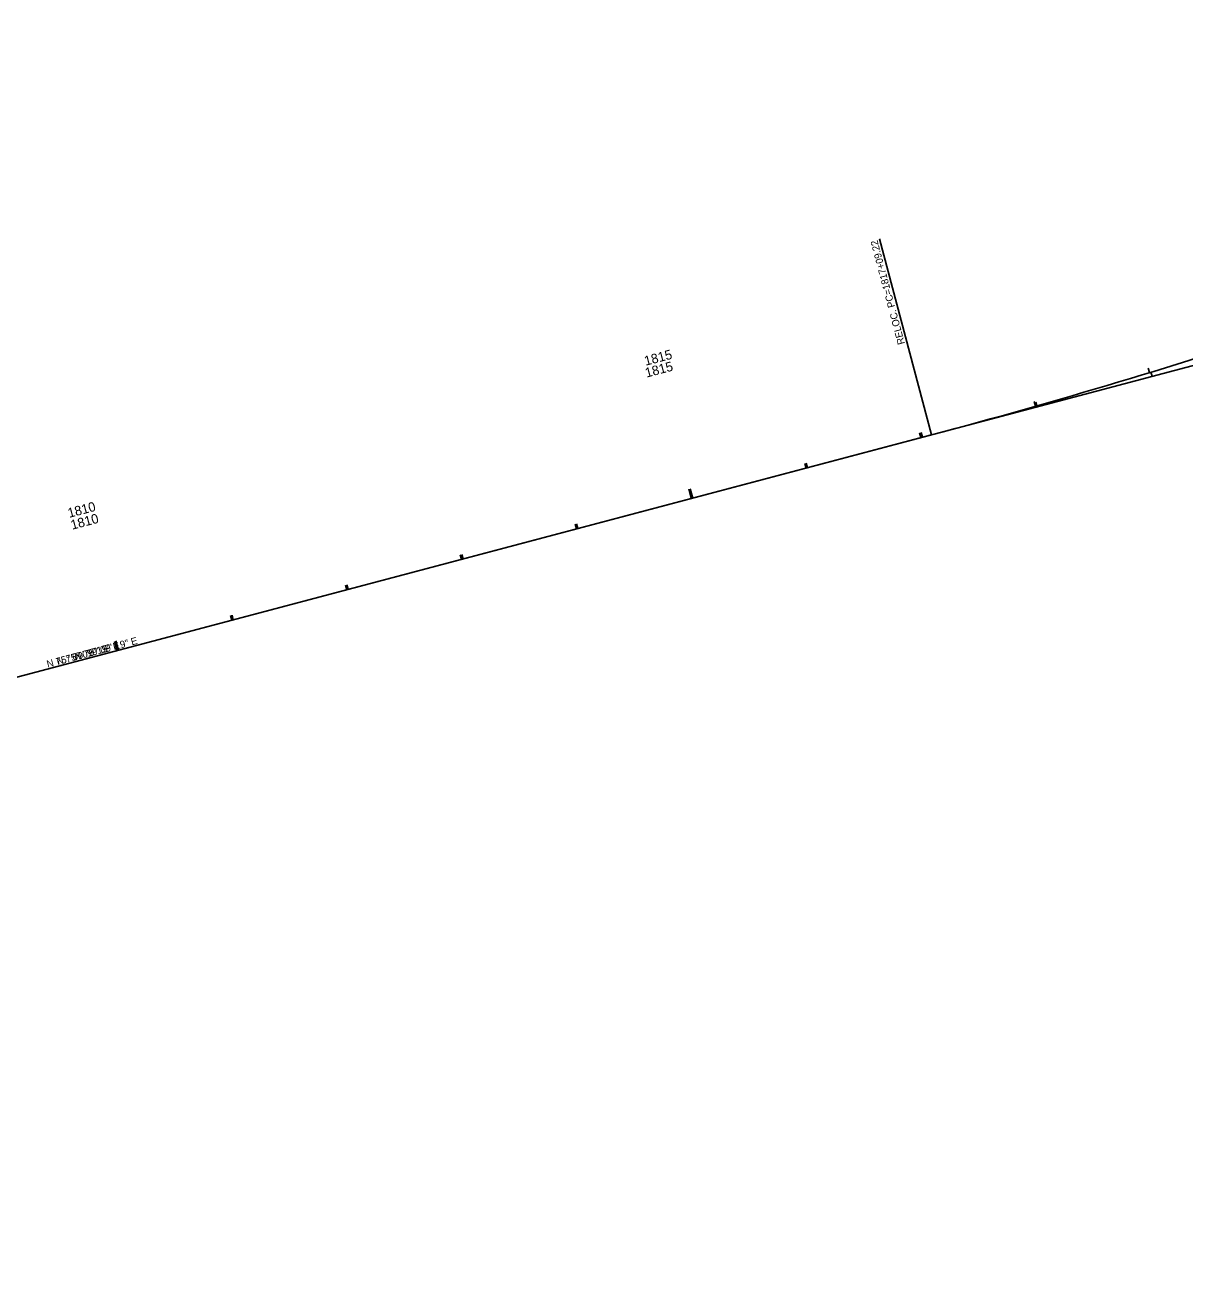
# Model space of a CAD drawing. Extents: x 2106154 to 2121963, y 864504 to 868517.
# Drawn here: x 2112014 to 2112990, y 867153 to 868210 of the extents above; entities that cross this region are included whole.
import ezdxf

# ---------------------------------------------------------------- set-up
doc = ezdxf.new("R2010")
doc.units = 0
for name, color, linetype in [('RD_HC_Cl', 7, 'Continuous'), ('RD_HC_CL_Rel', 7, 'Continuous'), ('RD_HC_Data', 7, 'Continuous'), ('RD_HC_Data_Rel', 7, 'Continuous'), ('RD_HC_Data_Tic', 7, 'Continuous'), ('RD_HC_Data_Tic_Rel', 7, 'Continuous'), ('RD_HC_TX_Rel_Sta50', 7, 'Continuous'), ('RD_HC_TX_Sta50', 7, 'Continuous')]:
    doc.layers.add(name, color=color, linetype=linetype)

msp = doc.modelspace()

# ---------------------------------------------------------------- linework, layer by layer
at = {"layer": 'RD_HC_Cl'}
msp.add_line((2110088.7, 867152.7), (2114077.7, 868210), dxfattribs=at)
at = {"layer": 'RD_HC_CL_Rel'}
msp.add_line((2111359.8, 867489.6), (2112776.4, 867865.1), dxfattribs=at)
msp.add_arc((2111482.6, 872746.5), 5050, 284.8448, 288.5627, dxfattribs=at)
at = {"layer": 'RD_HC_Data_Rel'}
msp.add_line((2112776.4, 867865.1), (2112732.6, 868030.1), dxfattribs=at)
at = {"layer": 'RD_HC_Data_Tic'}
for p, q in [((2112962, 867914.3), (2112961, 867918.2)), ((2112865.4, 867888.7), (2112864.3, 867892.5)), ((2112768.7, 867863.1), (2112767.7, 867866.9)), ((2112672, 867837.4), (2112671, 867841.3)), ((2112575.4, 867811.8), (2112573.3, 867819.6)), ((2112478.7, 867786.2), (2112477.7, 867790.1)), ((2112382.1, 867760.6), (2112381, 867764.4)), ((2112285.4, 867735), (2112284.4, 867738.8)), ((2112188.7, 867709.3), (2112187.7, 867713.2)), ((2112092.1, 867683.7), (2112090, 867691.5))]:
    msp.add_line(p, q, dxfattribs=at)
at = {"layer": 'RD_HC_Data_Tic_Rel'}
for p, q in [((2112959.8, 867917.4), (2112958.7, 867921.3)), ((2112863.9, 867889.1), (2112862.8, 867893)), ((2112767.5, 867862.7), (2112766.4, 867866.6)), ((2112670.8, 867837.1), (2112669.8, 867841)), ((2112574.1, 867811.5), (2112572.1, 867819.2)), ((2112477.5, 867785.9), (2112476.5, 867789.7)), ((2112380.8, 867760.3), (2112379.8, 867764.1)), ((2112284.2, 867734.6), (2112283.1, 867738.5)), ((2112187.5, 867709), (2112186.5, 867712.9)), ((2112090.8, 867683.4), (2112088.8, 867691.1))]:
    msp.add_line(p, q, dxfattribs=at)

# ---------------------------------------------------------------- texts
at = {"layer": 'RD_HC_Data'}
msp.add_text('N 75%%d 09\' 19" E', height=6, rotation=14.8448, dxfattribs=at).set_placement((2112056, 867675.2))
at = {"layer": 'RD_HC_Data_Rel'}
for s, rotation, p in [('RELOC. PC=1817+09.22', 104.8448, (2112754, 867941.9)), ('N 75%%d 09\' 19" E', 14.8448, (2112032.6, 867669)), ('N 75%%d 09\' 19" E', 14.8448, (2112040.9, 867671.2))]:
    msp.add_text(s, height=6, rotation=rotation, dxfattribs=at).set_placement(p)
at = {"layer": 'RD_HC_TX_Rel_Sta50'}
for s, p in [('1815', (2112535.8, 867923.2)), ('1810', (2112050.6, 867795.1))]:
    msp.add_text(s, height=8, rotation=14.8448, dxfattribs=at).set_placement(p)
at = {"layer": 'RD_HC_TX_Sta50'}
for s, p in [('1815', (2112536.5, 867913.2)), ('1810', (2112053.1, 867785.1))]:
    msp.add_text(s, height=8, rotation=14.8448, dxfattribs=at).set_placement(p)

doc.saveas('drawing.dxf')
